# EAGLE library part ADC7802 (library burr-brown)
12-Bit Analog to Digital Converter
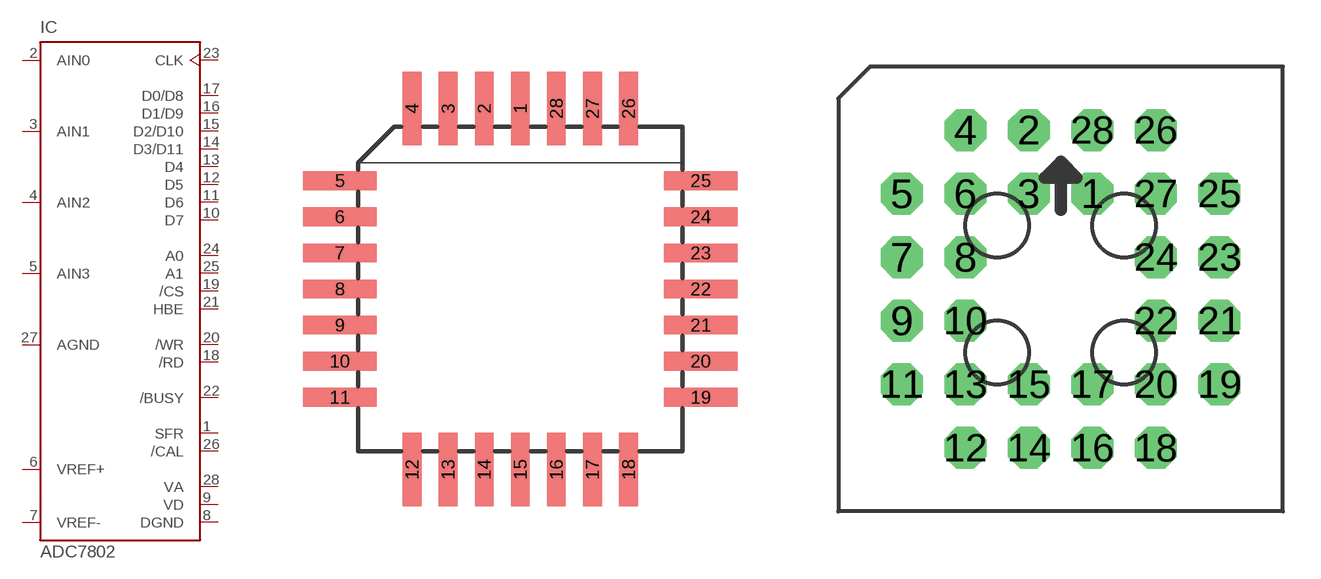
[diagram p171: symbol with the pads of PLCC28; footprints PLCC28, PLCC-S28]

Designator prefix IC

## ADC7802PLC (OC_FARNELL: unknown; OC_NEWARK: unknown)  [PLCC28]
1  SFR  pas
2  AIN0  in
3  AIN1  in
4  AIN2  in
5  AIN3  in
6  VREF+  in
7  VREF-  in
8  DGND  pas
9  VD  pas
10  D7  hiz
11  D6  hiz
12  D5  hiz
13  D4  hiz
14  D3/D11  hiz
15  D2/D10  hiz
16  D1/D9  hiz
17  D0/D8  hiz
18  /RD  in
19  /CS  in
20  /WR  in
21  HBE  in
22  /BUSY  out
23  CLK  in
24  A0  in
25  A1  in
26  /CAL  in
27  AGND  pas
28  VA  pas

## ADC7802PLC-S (OC_FARNELL: unknown; OC_NEWARK: unknown)  [PLCC-S28]
Pads as for PLCC28

## Footprint PLCC28 (pad centres in mm)
PLASTIC LEADED CHIP CARRIER square
smd 0.66 x 2.591: 1 0,6.35; 2 -1.27,6.35; 3 -2.54,6.35; 4 -3.81,6.35; 12 -3.81,-6.35; 13 -2.54,-6.35; 14 -1.27,-6.35; 15 0,-6.35; 16 1.27,-6.35; 17 2.54,-6.35; 18 3.81,-6.35; 26 3.81,6.35; 27 2.54,6.35; 28 1.27,6.35
smd 2.591 x 0.66: 5 -6.35,3.81; 6 -6.35,2.54; 7 -6.35,1.27; 8 -6.35,0; 9 -6.35,-1.27; 10 -6.35,-2.54; 11 -6.35,-3.81; 19 6.35,-3.81; 20 6.35,-2.54; 21 6.35,-1.27; 22 6.35,0; 23 6.35,1.27; 24 6.35,2.54; 25 6.35,3.81

## Footprint PLCC-S28 (pad centres in mm)
SOCKET Plastic leaded chip carrier, square
drill 0.813 pad 1.676 octagon: 1 1.27,3.81; 2 -1.27,6.35; 3 -1.27,3.81; 4 -3.81,6.35; 5 -6.35,3.81; 6 -3.81,3.81; 7 -6.35,1.27; 8 -3.81,1.27; 9 -6.35,-1.27; 10 -3.81,-1.27; 11 -6.35,-3.81; 12 -3.81,-6.35; 13 -3.81,-3.81; 14 -1.27,-6.35; 15 -1.27,-3.81; 16 1.27,-6.35; 17 1.27,-3.81; 18 3.81,-6.35; 19 6.35,-3.81; 20 3.81,-3.81; 21 6.35,-1.27; 22 3.81,-1.27; 23 6.35,1.27; 24 3.81,1.27; 25 6.35,3.81; 26 3.81,6.35; 27 3.81,3.81; 28 1.27,6.35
